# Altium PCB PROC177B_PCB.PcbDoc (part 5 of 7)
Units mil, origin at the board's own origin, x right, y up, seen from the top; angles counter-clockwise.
Board outline 4257.98 x 1561.15 mil, 4 copper layers (Top Layer, Int1 (GND), Int2 (PWR), Bottom Layer), stack 63.572 mil thick; 461 components, 307 nets, 1564 pads, 607 vias.
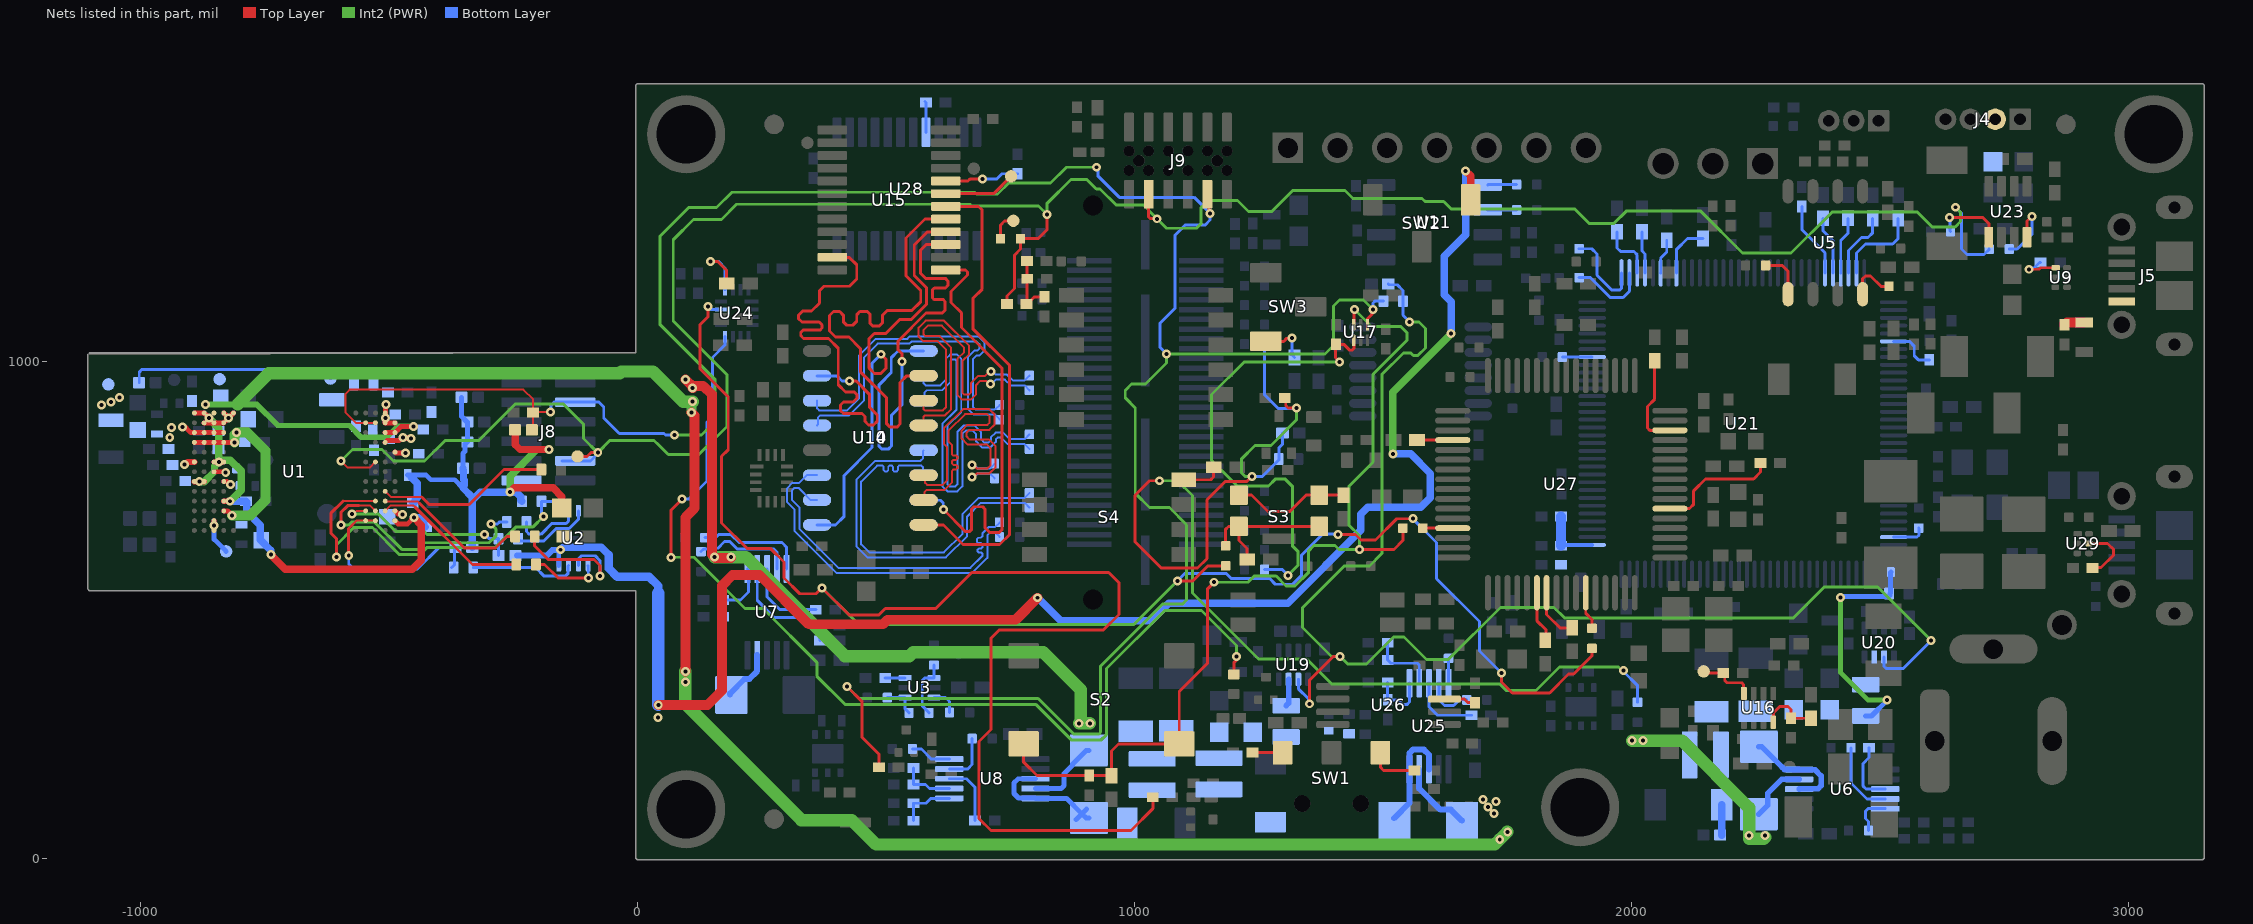
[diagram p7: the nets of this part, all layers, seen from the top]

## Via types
v1: diameter 18, hole 8, Top Layer to Bottom Layer, tented both sides, 603 vias
v2: diameter 19.68, hole 7.87, Top Layer to Bottom Layer, 4 vias

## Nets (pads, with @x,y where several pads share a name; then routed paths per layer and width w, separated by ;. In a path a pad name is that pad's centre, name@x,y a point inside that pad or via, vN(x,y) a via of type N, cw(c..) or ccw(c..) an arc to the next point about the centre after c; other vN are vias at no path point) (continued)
NetR16_2: R16.2 R206.2 R207.1 R208.2 | length 127.2
  Top Layer w5.9: R206.2@783.3,1115.15 785.27,1115.15 799.51,1129.39 R208.2@819.66,1129.39 ; R16.2@784.33,1201.3 784.33,1165.88 R207.1@784.59,1165.62 R206.2@784.59,1116.44
NetR18_2: R18.2 U23.1 | length 140.4
  Top Layer w5.9: v1(2640.07,1288.88) 2640.35,1288.6 2707.3,1288.6 2719.11,1276.8 U23.1@2719.11,1249.24
  Bottom Layer w5.9: v1(2640.07,1288.88) 2641.14,1287.82 2641.14,1262.05 R18.2@2642.2,1260.98
NetR19_2: R19.2 U23.4 | length 140
  Top Layer w5.9: U23.4@2795.88,1249.24 2795.88,1281.65 2805.38,1291.16 v1(2805.62,1291.16)
  Bottom Layer w5.9: R19.2@2760.28,1225.35 2776.11,1225.35 2805.62,1254.86 v1(2805.62,1291.16)
NetR25_1: R25.1 U6.5 | length 83.7
  Bottom Layer w5.9: R25.1@2477.18,55.6 2477.18,73.67 2470.87,79.98 2470.87,94.72 2475.82,99.67 U6.5@2510.78,99.67
NetR29_1: R29.1 U6.4 | length 152.7
  Bottom Layer w5.9: R29.1@2442.08,222.2 2442.08,151.44 2474.16,119.36 U6.4@2510.78,119.36
NetR33_2: R33.2 U24.13 | length 144.7
  Top Layer w5.9: v1(147.43,1200.04) 162.59,1200.04 180.11,1182.52 R33.2@180.11,1156.14
  Bottom Layer w5.9: v1(147.43,1200.04) 164.32,1200.04 176.78,1187.57 U24.13@176.78,1143.67
NetR45_1: R45.1 U2.5 | length 141.1
  Top Layer w5.9: R45.1@-203.66,591.06 -186.35,591.06 -159.4,564.1 v1(-98.28,564.1)
  Bottom Layer w5.9: U2.5@-98.86,588.39 -98.41,587.94 -98.41,564.23 v1(-98.28,564.1)
NetR46_2: R46.2 U2.2 | length 138
  Bottom Layer w6: R46.2@-222.82,676.58 -222.82,657.38 -217.43,652 -193,652 -171.8,673.2 -142.8,673.2 -137.9,678.1 U2.2@-137.9,698.95
NetR47_2: R47.2 U2.3 | length 158.8
  Bottom Layer w5.9: R47.2@-239.59,642.85 -234.53,637.78 -188.25,637.78 -162.79,663.25 -136.81,663.25 -118.22,681.85 U2.3@-118.22,698.95
NetR48_1: R48.1 U2.6 | length 282.8
  Top Layer w5.9: R48.1@-206.11,647.29 -206.11,628.4 -178.8,601.1 -87.03,601.1 -74.55,588.62 v1(-74.55,567.71)
  Bottom Layer w5.9: U2.6@-118.22,588.71 -118.22,602.49 -112.18,608.52 -84.5,608.52 -74.55,598.58 v1(-74.55,567.71)
NetR51_1: R51.1 U2.7 | length 216.5
  Bottom Layer w5.9: R51.1@-329.74,584.82 -204.43,584.82 -186.96,567.36 -144.66,567.36 -138.75,573.27 -138.75,587.87 U2.7@-137.9,588.71
NetR54_1: R54.1 U3.3 | length 40
  Bottom Layer w5.9: R54.1@498.95,362.69 U3.3@538.95,362.69
NetR55_2: R55.2 U3.6 | length 56.7
  Bottom Layer w5.9: U3.6@597.22,323.32 620.3,323.32 628.46,315.16 R55.2@628.46,293.12
NetR56_2: R56.2 R151.1 U3.1 | length 70
  Bottom Layer w5.9: R56.2@503.22,323.15 503.31,323.24 538.87,323.24 U3.1@538.95,323.32 538.95,300.75 546.82,292.88 R151.1@546.82,292.39
NetR57_1: R57.1 R151.2 U3.4 | length 122.7
  Bottom Layer w5.9: R151.2@587.17,292.39 587.17,292.88 573.51,306.54 573.51,357.59 578.61,362.69 U3.4@597.22,362.69 597,362.91 R57.1@597,388.66
NetR70_1: R70.1 S4.8 | length 81.4
  Top Layer w5.9: S4.8@1099.68,761.36 1153.76,761.36 1159.61,767.21 R70.1@1159.61,786.29
NetR72_2: R72.2 U9.1 | length 88.4
  Top Layer w5.9: v1(2799.93,1184.83) 2819.83,1184.83 2822.94,1187.94 U9.1@2857.94,1187.94
  Bottom Layer w5.9: v1(2799.93,1184.83) 2802.25,1187.14 2809.89,1187.14 2821.34,1198.6 R72.2@2823.31,1198.6
NetR78_2: R78.2 U5.1 | length 96.1
  Top Layer w5.9: R78.2@2270.11,1192.52 2303.76,1192.52 2315.27,1181 U5.1@2315.27,1134.88
NetR80_2: R80.2 U5.4 | length 95.1
  Top Layer w5.9: U5.4@2465.27,1134.88 2465.27,1165.84 2470.97,1171.54 2481.14,1171.54 2502.08,1150.59 R80.2@2518.4,1150.59
NetR83_2: R83.2 SW3.3 | length 96.6
  Top Layer w5.9: SW3.3@1264.64,1040.37 1265.47,1039.53 1300.53,1039.53 1307,1046 1317.13,1046 v1(1317.26,1046.12)
  Bottom Layer w5.9: v1(1317.26,1046.12) 1317.26,1012.73 R83.2@1322.56,1007.42
NetR93_2: R93.2 U1.E2 | length 350.3
  Top Layer w4: U1.E2@-506.87,738.15 -495.62,726.9 -433.56,726.9
  Top Layer w5.9: -433.56,726.9 -418.35,711.69 -337.98,711.69 -267.78,781.9 R93.2@-196.58,781.9
NetR94_2: R94.2 U6.3 | length 129.1
  Bottom Layer w5.9: R94.2@2478.02,222.27 2478.02,202.58 2466.3,190.86 2466.3,144.96 2472.22,139.04 U6.3@2510.78,139.04
NetR104_1: R104.1 R113.2 U7.2 | length 240.1
  Bottom Layer w5.9: U7.2@241.62,581.8 241.62,518.78 276.54,483.86 322.49,483.86 338.56,467.79 R104.1@367.76,467.79 R113.2@367.76,437.96
NetR105_1: R105.1 R114.2 U7.1 | length 138.6
  Bottom Layer w5.9: R105.1@172.68,485.6 R114.2@172.68,519.6 207.7,519.6 223.77,535.66 223.77,579.97 U7.1@221.94,581.8
NetR106_1: R106.1 R116.2 U8.2 | length 108.8
  Bottom Layer w5.9: R116.2@555.68,181.6 R106.1@555.68,148.6 580,148.6 588.37,140.23 U8.2@628.05,140.23
NetR107_1: R107.1 R117.2 U8.1 | length 111.5
  Bottom Layer w5.9: R117.2@555.68,75.6 R107.1@555.68,110.6 580.91,110.6 590.84,120.53 U8.1@628.05,120.54
NetR108_1: R108.1 U7.5 | length 221.2
  Bottom Layer w5.9: R108.1@136.19,644.91 157.8,644.91 163.76,650.87 189.13,650.87 204.87,635.13 291.16,635.13 300.68,625.62 U7.5@300.68,581.8
NetR109_1: R109.1 U8.5 | length 82.8
  Bottom Layer w5.9: R109.1@553.74,219.86 571.74,219.86 592.31,199.28 U8.5@628.05,199.28
NetR110_1: R110.1 U7.4 | length 203.6
  Bottom Layer w5.9: R110.1@128.61,616.82 134.08,622.29 147.3,622.29 148.56,623.55 162.53,623.55 175.9,636.92 186.25,636.92 200.64,622.53 274.52,622.53 280.99,616.06 U7.4@280.99,581.8
NetR111_1: R111.1 U8.4 | length 101.6
  Bottom Layer w5.9: U8.4@628.05,179.6 665,179.6 673.82,188.43 R111.1@673.82,240.6
NetR112_2: R112.2 U7.3 | length 164.6
  Bottom Layer w5.9: U7.3@261.31,581.8 261.31,525.98 287.28,500 R112.2@359.34,500
NetR115_2: R115.2 U8.3 | length 125.6
  Bottom Layer w5.9: U8.3@628.05,159.91 662.69,159.91 679.84,142.76 R115.2@679.84,76.05
NetR122_1: R122.1 U21.35 | length 114.9
  Bottom Layer w5.9: R122.1@1971.24,1260.16 1971.24,1227.81 1978.71,1220.34 2005.3,1220.34 2011.8,1213.85 U21.35@2011.8,1177.6
NetR124_1: R124.1 U21.36 | length 85.2
  Bottom Layer w5.9: R124.1@2021.22,1260.16 2021.22,1221.93 2027.55,1215.6 U21.36@2027.55,1177.6
NetR125_1: R125.1 U21.38 | length 70.4
  Bottom Layer w5.9: U21.38@2059.04,1177.6 2059.17,1177.73 2059.17,1207.38 2071.2,1219.4 R125.1@2071.2,1242.93
NetR126_1: R126.1 U21.40 | length 109.5
  Bottom Layer w5.9: U21.40@2090.54,1177.6 2090.54,1224.17 2113.12,1246.75 R126.1@2144.09,1246.75
NetR135_1: R135.1 R148.2 U25.2 | length 139.1
  Bottom Layer w5.9: R148.2@1509.86,433.69 R135.1@1509.86,398.71 1516.33,392.24 1569.81,392.24 1573.27,388.78 U25.2@1573.27,352.18
NetR136_1: R136.1 R150.2 U25.1 | length 122.9
  Bottom Layer w5.9: R136.1@1509.86,353.71 R150.2@1509.86,318.71 1530.55,318.71 1540.39,308.87 1548.16,308.87 1553.58,314.3 U25.1@1553.58,352.18
NetR137_1: R137.1 U25.5 | length 50
  Bottom Layer w5.9: U25.5@1632.32,352.18 R137.1@1632.32,402.18
NetR139_1: R139.1 U25.4 | length 98.7
  Bottom Layer w5.9: U25.4@1612.64,352.18 1612.92,351.9 1612.92,318.43 1623.85,307.5 1642.51,307.5 1653.93,318.92 R139.1@1668.51,318.92
NetR142_2: R142.2 U25.3 | length 140
  Bottom Layer w5.9: U25.3@1592.95,352.18 1592.95,304.65 1610,287.6 R142.2@1678.31,287.6
NetR159_1: R159.1 U11.6 | length 58.3
  Bottom Layer w5.9: U11.6@1711.14,1304.47 1711.51,1304.1 R159.1@1769.3,1304.1
NetR160_1: R160.1 U11.5 | length 58.5
  Bottom Layer w5.9: U11.5@1711.14,1354.47 1712.04,1355.38 R160.1@1769.3,1355.38
NetR170_1: R170.1 U21.95 | length 66.9
  Bottom Layer w5.9: U21.95@2527.55,646.1 2574.77,646.1 2578.53,649.85 2578.53,663.62 R170.1@2578.12,664.03
NetR181_2: R181.2 U21.33 | length 177.2
  Bottom Layer w5.9: R181.2@1895.06,1226.06 1920.17,1226.06 1930.64,1215.58 1930.64,1172.96 1960.63,1142.97 1976.85,1142.97 1980.3,1146.43 U21.33@1980.3,1177.6
NetR185_2: R185.2 U26.3 | length 64.8
  Top Layer w5.9: U26.3@1623.99,320.19 1663.91,320.19 1670.4,313.7 1684.73,313.7 R185.2@1685.72,312.7
NetR188_2: R188.2 U21.34 | length 159.5
  Bottom Layer w5.9: R188.2@1895.07,1167.93 1917.94,1167.93 1957.62,1128.25 1983.62,1128.25 1996.05,1140.68 U21.34@1996.05,1177.6
NetR190_2: R190.2 U21.25 | length 60
  Bottom Layer w5.9: R190.2@1861.25,1008.31 U21.25@1921.25,1008.31
NetR191_1: R191.1 U21.63 | length 176
  Bottom Layer w5.9: U21.63@2452.74,1177.6 2452.74,1217.35 2471.07,1235.67 2525.66,1235.67 2536.85,1246.87 R191.1@2536.85,1286.8
NetR194_1: R194.1 U21.62 | length 136.8
  Bottom Layer w5.9: U21.62@2437,1177.6 2437,1222.6 2463,1248.6 2475.83,1248.6 2485.43,1258.2 R194.1@2485.43,1286.8
NetR195_1: R195.1 U21.61 | length 115.7
  Bottom Layer w5.9: U21.61@2421.25,1177.6 2421.25,1242.42 2436.08,1257.25 R195.1@2436.08,1287.14
NetR196_1: R196.1 U21.60 | length 117.8
  Bottom Layer w5.9: R196.1@2385.51,1287.14 2385.51,1262.34 2405.5,1242.35 U21.60@2405.5,1177.6
NetR213_1: R213.1 S3.3 S3.4 | length 237.6
  Top Layer w5.9: S3.4@1210.66,730.49 1236.14,730.49 1269.21,697.43 1312.82,697.43 1345.89,730.49 S3.3@1372.08,730.49 R213.1@1420.9,730.49
NetR214_1: R214.1 R215.1 S3.1 S3.2 | length 297.2
  Top Layer w5.9: R214.1@1184,628.54 1184,661.93 1189.58,667.5 S3.2@1210.66,667.5 ; R215.1@1227.05,600.84 1227.05,623 1210.66,639.4 S3.2@1210.66,667.5 ; S3.1@1372.08,667.5 S3.2@1210.66,667.5
NetR231_1: R231.1 U21.70 | length 98.4
  Bottom Layer w5.9: U21.70@2527.55,1039.81 2559.36,1039.81 2569.16,1030 2569.16,1010.95 2577.38,1002.73 R231.1@2599.45,1002.73
NetR234_2: R234.2 U21.59 | length 152.9
  Bottom Layer w5.9: R234.2@2342.87,1311.08 2342.87,1264.73 2389.75,1217.85 U21.59@2389.75,1177.6
NetR242_1: R242.1 U27.59 | length 76.7
  Top Layer w5.9: U27.59@1908.32,534.06 1908.32,492.71 1920.74,480.3 R242.1@1920.74,462.51
NetR251_1: R251.1 U27.36 | length 71.8
  Top Layer w5.9: R251.1@1568.79,841.15 U27.36@1640.61,841.15
NetR260_2: R260.2 U29.5 | length 118.8
  Top Layer w5.9: U29.5@2920.73,633.09 2958.12,633.09 2970.36,620.85 2970.36,610.29 2944.87,584.8 2928.39,584.8 R260.2@2927.66,584.07
NRST_FTDI: R243.1 U27.45 | length 60
  Top Layer w5.9: R243.1@1580.61,663.99 U27.45@1640.61,663.99
PGOOD: R58.1 R179.1 R198.1 R201.2 R241.1 | length 2441.1
  Top Layer w5.9: v1(1050.82,759.39) 1030.81,759.39 1001.55,730.13 1001.55,636.49 1054.29,583.76 1127.19,583.76 1146.12,602.68 1146.12,721.1 1183.33,758.31 1226.93,758.31 1236.44,767.82 v1(1236.44,767.93) ; R179.1@1302.99,925.75 1304.79,923.95 1304.79,910.51 1309.48,905.83 v1(1326.6,905.83)
  Int2 (PWR) w5.9: v1(1050.82,759.39) 1087.71,759.39 1117.26,729.84 1117.26,533.58 1249.84,401 1346.94,401 1397.01,350.93 1735.05,350.93 1748.36,337.62 1808.26,337.62 1855.27,384.64 1973.95,384.64 1980.96,377.64 v1(1984.11,377.64) ; v1@1236.28,768.08 1223.14,768.08 1215.32,775.91 1215.32,802.82 1242.83,830.33 1274.89,830.33 1326.6,882.05 v1(1326.6,905.83)
  Bottom Layer w5.9: v1(1236.44,767.93) 1257.68,767.93 1290.81,801.06 1290.81,825.16 1298.43,832.78 R201.2@1298.43,855.52 ; R58.1@1262.19,1034.29 1262.19,932.26 1289.42,905.03 1325.81,905.03 v1(1326.6,905.83) ; v1(1984.11,377.64) 1984.11,375.5 2012.67,346.94 2012.67,314.14 R241.1@2012.34,313.81
PMIC_CLKOUT: R15.2 TP1.1 | length 56.6
  Top Layer w5.9: R15.2@730.92,1246.42 730.92,1273.51 739.07,1281.66 756,1281.66 TP1.1@756.73,1282.4
PMIC_CLKOUT_LIN_PHY_TX_SOP1: J8.4 J9.3 R15.1 R19.1 R206.1 TP13.1 U1.H3 | length 4957
  Top Layer w4: v1(-595.63,799.05) -582.15,785.57 -538.19,785.57 U1.H3@-526.56,797.2
  Top Layer w5.9: TP13.1@-119.98,808.16 -100.84,808.16 -93.1,815.9 v1(-79.24,815.9) ; R206.1@743.93,1115.15 743.93,1131.09 759.04,1146.2 759.04,1213.19 771.27,1225.41 R15.1@771.27,1246.42 806.49,1246.42 824.85,1264.78 v1(824.85,1295) ; J9.3@1028.99,1335.77 1028.99,1289.98 1032.45,1286.53 v1@1045.9,1286.53
  Int2 (PWR) w5.9: v1(-595.63,799.05) -572.55,822.12 -513.3,822.12 -490.18,799.01 -427.58,799.01 -386.58,840 -319.28,840 -245.79,913.49 -163.25,913.49 -148.05,913.49 -107.67,873.11 -107.67,844.34 v1(-79.24,815.9) -54.41,840.74 32.47,840.74 32.62,840.59 34.13,840.59 43.64,831.08 62.7,812.01 124.04,812.01 180.78,868.76 180.78,972.62 72.66,1080.74 72.66,1244.11 113.6,1285.05 169.52,1285.05 200.06,1315.59 669.41,1315.59 672.77,1312.24 807.62,1312.24 v1(824.85,1295) 824.85,1317.82 872.65,1365.62 904.56,1365.62 923.67,1346.51 931.15,1346.51 963.76,1313.9 1018.53,1313.9 v1(1046.03,1286.4) 1065.04,1267.39 1125.21,1267.39 1134.69,1276.87 1134.69,1309.12 1148.65,1323.07 1207.94,1323.07 1229.84,1301.18 1276.78,1301.18 1318.84,1343.23 1424.12,1343.23 1440.19,1327.17 1579.08,1327.17 1585.31,1320.94 1622.47,1320.94 1637,1306.41 1885.64,1306.41 1915.38,1276.66 1964.62,1276.66 1989.62,1301.65 2139.59,1301.65 2223.81,1217.43 2321.45,1217.43 2403.63,1299.62 2575.78,1299.62 2605.31,1270.09 2651.47,1270.09 2662.21,1280.83 2662.21,1299.56 v1(2652.17,1309.61)
  Bottom Layer w5.9: J8.4@-150.85,799.4 J8.4@-124.58,799.4 -94.07,799.4 -79.24,814.23 v1(-79.24,815.9) ; v1(2652.17,1309.61) 2664.21,1297.57 2664.21,1225.69 2675.41,1214.5 2709.56,1214.5 2719.92,1224.86 R19.1@2719.92,1225.35
QSPI_CS: R50.2 U1.D3 U2.1 | length 784.2
  Top Layer w4: -591.91,718.26 U1.D3@-526.76,718.26
  Top Layer w5.9: v1(-604.99,605.87) -604.99,642.83 -616.25,654.09 -616.25,693.92 -591.91,718.26
  Int2 (PWR) w5.9: v1(-604.99,605.87) -604.99,630.38 -570.31,665.07 -532.68,665.07 -478.94,611.33 -436.83,611.33 -423.46,624.7 -285.52,624.7 -244.17,666.05 -210.18,666.05 v1(-188.64,687.59)
  Bottom Layer w5.9: R50.2@-192.32,717.93 -161.94,717.93 -157.59,713.57 U2.1@-157.59,698.95 ; R50.2@-192.2,717.8 -192.2,693.86 -188.64,690.3 v1(-188.64,687.59)
QSPI_D0: R45.2 U1.C2 | length 313.9
  Top Layer w4: U1.C2@-506.87,698.78 -495.61,710.04 -450.46,710.04 -446.57,706.16
  Top Layer w5.9: -446.57,706.16 -331.48,591.06 R45.2@-246.96,591.06
QSPI_D1: R46.1 U1.C3 | length 515.1
  Top Layer w4: -559.75,709.31 -559.22,709.83 -537.61,709.83 U1.C3@-526.56,698.78
  Top Layer w5.9: v1(-595.52,670.61) -595.52,696.2 -582.41,709.31 -559.75,709.31
  Int2 (PWR) w5.9: v1(-595.52,670.61) -580.27,670.61 -574.83,676.05 -528.11,676.05 -473.47,621.41 -440.75,621.41 -427.56,634.6 -297.81,634.6 -283.59,648.83 -283.59,661.62 v1(-294.45,672.47)
  Bottom Layer w5.9: v1(-294.45,672.47) -280.97,672.47 -277.42,676.02 -262.75,676.02 R46.1@-262.19,676.58
QSPI_D2: R44.1 R47.1 U1.C4 | length 379
  Top Layer w4: v1(-573.43,692.83) -569.64,692.83 -563.69,698.78 U1.C4@-546.24,698.78
  Int2 (PWR) w5.9: v1(-573.43,692.83) -521.25,692.83 -486.02,657.6 -428.9,657.6 -422.79,651.49 v1(-307.01,651.49)
  Bottom Layer w5.9: v1(-307.01,651.49) -306.3,651.49 -297.66,642.85 R47.1@-278.96,642.85 -278.96,609.26 R44.1@-278.56,608.86
QSPI_D3: R49.1 R51.2 U1.B3 U1.B4 | length 409.5
  Top Layer w4: -572.63,671.09 -564.62,679.09 U1.B3@-526.56,679.09
  Top Layer w5.9: v1(-580.2,609.1) -580.51,609.41 -580.51,663.39 -572.82,671.09 -572.63,671.09
  Bottom Layer w5.9: v1(-580.2,609.1) -580.2,592.18 -569.65,581.62 -442.02,581.62 -398.19,625.44 -368.27,625.44 -367.55,624.72 -367.55,590.32 R51.2@-373.05,584.82
QSPI_SCLK: R48.2 U1.D2 | length 309.9
  Top Layer w4: U1.D2@-506.84,718.5 -506.38,718.04 -441.62,718.04 -437.71,714.13
  Top Layer w5.9: -437.71,714.13 -347.85,624.27 -284.85,624.27 -261.82,647.29 R48.2@-245.48,647.29
RADAR_1P2_RF: C20.2 C24.2 C44.1 C101.2 R134.2 TP16.1 U1.L7 U1.L8 U1.L9 U1.L10 U25.9 | length 239.3
  Top Layer w10: v1(-915.04,867.23) -913.89,866.09 -907.8,866.09 -897.98,856.26 U1.L9@-871.04,856.26 U1.L8@-851.36,856.26 U1.L7@-831.67,856.26
  Bottom Layer w12: U25.9@1573.27,178.95 1573.27,140.27 1615.72,97.82 1636.87,97.82 R134.2@1659.17,75.52
  other v1: 1724.05,90.44 1711.42,103.17 1727.65,114.48 1701.87,118.61 -940.29,846.58 -937.03,866.57 -1077.9,912.16 -1058.76,917.66 -1041.29,926.5
RADAR_1V2: C27.2 C28.2 C29.2 C30.1 C45.1 R77.2 R86.2 R193.2 TP15.1 U1.K2 U8.9 | length 2001.4
  Top Layer w10: U1.K2@-506.87,836.57 -503.43,840.02 -479.09,840.02 -473.25,845.85 v1@-470.97,845.85
  Top Layer w12: v1(-470.97,846.51) -470.2,845.75 -457.77,845.75 -456.34,844.31 v1(-455.26,844.31)
  Top Layer w15: v1(-470.97,846.51) v1@-470.7,846.51
  Top Layer w20: v1(97.5,963.14) 97.5,963.09 111.73,948.85 v1(111.73,946.37) ; v1@112.5,946.37 116.27,950.14 132.84,950.14 150.26,932.72 150.26,611.34 157.54,604.06 v1@188.58,604.06
  Int2 (PWR) w25: v1(156,605.6) v1(188.58,605.6) 218.73,605.6 417.91,406.43 547.48,406.43 555.14,414.08 817.17,414.08 892.23,339.02 v1@892.23,271.53 ; v1(888.85,271.53) v1@892.23,271.53 ; v1(910.85,271.53) v1@892.23,271.53
  Bottom Layer w5.9: R86.2@-1001.58,956.6 -1001.58,977.81 -995.86,983.53 -635.71,983.53 TP15.1@-617.14,964.95
  Bottom Layer w10: U8.9@801.28,140.23 852.96,140.23 858.82,146.09 858.82,170.3 875.72,187.2 875.72,189.41 903.2,216.89 R193.2@908.71,216.89
RADAR_1V4_APLL: C22.2 U1.G8 | length 22.8
  Top Layer w10: U1.G8@-851.36,777.52 -829.67,777.52 v1@-829.67,776.38
  other v1: -827.67,776.38
RADAR_1V4_SYNTH: C18.2 U1.F7 | length 16.5
  Top Layer w10: U1.F7@-831.67,757.83 -825.39,757.83 -819.28,751.73 v1(-817.66,751.73)
RADAR_1V8: C4.2 C5.2 C7.2 C8.2 C10.2 C11.2 C12.2 C13.1 C14.2 C15.1 R192.2 TP14.1 U1.B1 U1.D7 U1.F9 U1.F10 U1.H7 U1.H8 U1.L1 U1.L2 U1.M7 U1.M8 U1.M9 U1.N6 U1.N7 U1.N8 U1.N9 U1.N10 U6.9 | length 5504.3
  Top Layer w10: U1.N10@-890.73,895.63 -881.2,895.63 -880.89,895.31 -880.57,895.63 U1.N9@-871.04,895.63 v1(-861.2,885.79) ; U1.M9@-871.04,875.94 U1.M8@-851.36,875.94 -832.54,875.94 U1.M7@-832.27,875.67 ; U1.H8@-851.36,797.2 U1.H7@-831.67,797.2 ; U1.M7@-831.67,875.94 v1(-821.83,885.79) ; U1.N7@-831.67,895.63 v1(-821.83,885.79) ; U1.N6@-811.99,895.63 v1(-821.83,885.79) ; U1.L2@-506.87,856.26 U1.L1@-486.41,856.26 ; U1.B1@-487.19,679.09 -480.76,672.67 -461.47,672.67 v1(-448.8,685.34) ; U1.L1@-487.19,856.26 -481.5,861.94 -481.39,861.94 -474.67,868.66 v1(-450.25,868.66)
  Top Layer w11: U1.F10@-890.73,757.83 U1.F9@-871.04,757.83 ; U1.D7@-831.67,718.46 -819.06,718.46 v1(-818.76,718.16)
  Top Layer w15: v1(-736.28,610.68) -736.28,609.87 -707.6,581.2 -452.41,581.2 -434.01,599.6 -434.01,670.27 -448.8,685.07 v1(-448.8,685.34)
  Top Layer w20: v1(97,375.96) 96.98,685.87 115.35,704.24 115.35,890.53 v1(109.19,896.69)
  Int2 (PWR) w11: -765.27,913.22 -722.57,870.52 -578.72,870.52 -555.04,846.84 -504.11,846.84 -482.29,868.66 v1(-450.25,868.66)
  Int2 (PWR) w12: v1(-868.7,913.22) -803.76,913.22 -765.27,913.22
  Int2 (PWR) w15: v1(-880.89,757.52) -870.75,757.52 -850.23,778.04 -850.23,788.18 v1(-841.52,796.89) ; v1(-861.2,885.79) -861.2,884.97 -841.52,865.29 v1(-841.52,796.89) ; v1(-818.76,718.16) -796.75,740.16 -796.75,779.1 -818.43,800.78 -836.81,800.78 -840.7,796.89 v1(-841.52,796.89)
  Int2 (PWR) w20: v1(109.19,896.69) 109.19,916.05 v1(111.73,918.6)
  Int2 (PWR) w25: -803.76,913.22 -740.93,976.05 -35.04,976.05 -31.87,979.22 31.91,979.22 92.53,918.6 v1(111.73,918.6) ; v1(97,375.96) 96.94,375.9 v1(96.94,354.46) 96.94,310.27 330.42,76.78 431.55,76.78 480.68,27.65 1725.04,27.65 v1(1735.27,37.88) v1@1750.3,52.91 ; v1(2001.72,236.57) 2101.89,236.6 2237,101.5 2237,42 2237,39.02 2266.06,39.02 v1@2269.04,42
  Bottom Layer w11: R192.2@2256.59,88.69 2274.69,106.78 2274.69,131.22 2302.2,158.73 U6.9@2337.55,158.73
  Bottom Layer w15: v1(-818.76,718.16) C14.2@-786.88,718.18 -784.93,716.23 -784.93,696.66 -758.06,669.78 -758.06,640.36 -736.85,619.15 -736.85,611.25 v1(-736.28,610.68) ; v1(-448.8,685.34) -448.61,685.14 -438.04,685.14 -428.94,676.05 -428.94,668.65 -426.6,666.31 C7.2@-425.94,666.31
  other v1: 2237,46 2269.04,46 1751.33,52.91 2023.72,236.6
RADAR_1V_RF_OUT: C9.2 C19.2 C23.1 U1.C7 U1.K7 U1.K8 U1.K9 U1.K10 | length 375.2
  Top Layer w10: U1.K10@-890.73,836.57 U1.K9@-871.04,836.57 U1.K8@-851.36,836.57 U1.K7@-831.67,836.57 v1(-810.17,836.52) v1(-810.17,836.52) ; U1.C7@-831.67,698.78 -823.85,698.78 v1(-814.95,689.89)
  Int2 (PWR) w20: v1(-814.95,689.89) -777.53,689.89 -748.04,719.38 -748.04,820.17 -783.95,856.08 v1(-806.23,856.08) -810.17,852.14 v1(-810.17,836.52)
RADAR_3V3: C16.2 C17.2 C21.2 C34.1 C35.2 C43.1 J8.1 R4.2 R20.2 R44.2 R49.2 R50.1 R73.2 R74.2 R75.2 R200.2 SW2.1 U1.C1 U1.J1 U2.8 U7.9 | length 4589.4
  Top Layer w10: U1.C1@-487.19,698.78 -480.68,692.27 -473.24,692.27 v1(-472.09,691.13) ; U1.J1@-487.19,816.89 -485.3,815.01 v1(-465.87,815.01)
  Top Layer w15: v1(-255.67,736.62) -247.3,744.99 -168.85,744.99 -151.48,727.62 C35.2@-151.48,704.58 ; R20.2@-245.67,861.86 -245.67,832.27 -235.64,822.24 v1(-177.61,822.24) ; v1(1666.78,1382.71) 1666.78,1382.29 1676.53,1372.54 SW2.1@1676.53,1324.48
  Top Layer w20: v1(42.47,308.38) 141.77,308.38 170.66,337.26 170.66,548.23 192.01,569.58 246.33,569.58 345.14,470.77 494.5,470.77 503.56,479.82 761.44,479.82 v1(805.66,524.05)
  Int2 (PWR) w15: v1(-255.67,736.62) -255.67,768.53 -201.96,822.24 v1(-177.61,822.24) ; v1(1520.16,813.4) 1520.16,937.82 1637.49,1055.15 v1(1637.49,1055.81)
  Bottom Layer w9: U2.8@-157.59,588.71 -157.59,615.34 -154.21,618.71 v1(-154.21,620.6)
  Bottom Layer w10: C17.2@-461.85,770.72 -424.55,770.72 -415.25,761.43 -366.94,761.43 -350.36,744.85 ; R74.2@-353.48,927.39 -353.48,889 -342.22,877.74 R75.2@-341.38,877.74 -341.49,877.64 -341.49,837.64 R4.2@-341.59,837.53 -346.18,832.94 -346.18,818.65 -350.36,814.48 R73.2@-350.36,784.56
  Bottom Layer w12: R44.2@-242,608.86 -181.76,608.86 -170.78,619.84 -154.98,619.84 v1(-154.21,620.6) ; R200.2@186.98,329.41 186.98,331.47 215.99,360.48 225.69,360.48 241.53,376.31 241.53,408.48 U7.9@241.62,408.58
  Bottom Layer w15: C17.2@-454.49,766.41 -442.13,754.05 -442.13,725.51 -446.91,720.73 -446.91,716.72 -449.25,714.38 C16.2@-451.22,714.38 ; R73.2@-350.36,784.56 -350.36,781.82 -349.34,780.8 -349.34,761.51 -348.03,760.2 -348.03,749.84 -350.36,747.51 -350.36,744.85 -331.72,726.21 ; R49.2@-331.72,625.44 -331.72,726.21 ; R50.1@-231.69,717.93 -234.03,720.27 -234.03,727.55 -243.11,736.62 v1(-255.67,736.62) -315.68,736.62 -328.9,723.4 -331.72,726.21 ; v1(-154.21,620.6) -153.94,620.6 -148.74,625.81 -72.54,625.81 -56.87,610.13 ; v1(805.66,524.05) 851.84,477.87 1034.17,477.87 1069.56,513.27 1309.25,513.27 1455.69,659.71 1455.69,691.88 1469.81,706 1576.72,706 1595.75,725.03 1595.75,773.96 1556.31,813.4 v1(1520.16,813.4) ; v1(1637.49,1055.81) 1637.65,1055.98 1637.65,1119.66 1623.88,1133.44 1623.88,1172.1 1623.43,1172.54 1623.43,1211.2 1666.78,1254.55 v1(1666.78,1382.71)
  Bottom Layer w17: -56.87,610.13 -56.87,582.87 -40.25,566.25 23.99,566.25 42.58,547.66 42.58,533.02
  Bottom Layer w25: v1(42.47,308.38) 42.47,532.91 42.58,533.02
  other v1: 42.03,283.22
RADAR_LVDS_0M: R230.2 U10.3 | length 675.4
  Bottom Layer w4: U10.3@361.83,770.53 341.33,770.53 325.76,754.96 312.35,754.96 301.56,744.18 301.56,716.34 316.25,701.65 316.25,658.63 400.76,574.12 674.51,574.12 704.69,604.3 704.69,649.62 710.96,655.9 719.71,655.9 729.06,646.55 R230.2@729.06,646.05
RADAR_LVDS_0P: R229.2 U10.2 | length 675.4
  Bottom Layer w4: U10.2@361.83,720.53 349.02,720.53 324.59,744.96 316.49,744.96 311.56,740.03 311.56,720.48 326.25,705.79 326.25,662.77 404.9,584.12 670.37,584.12 694.69,608.44 694.69,612.63 692.34,614.97 687.42,614.97 685.08,617.32 685.08,620.63 687.75,623.3 692.34,623.3 694.69,625.64 694.69,630.83 691.12,634.4 685.6,634.4 683.26,636.74 683.26,642.05 685.95,644.74 691.53,644.74 694.69,647.89 694.69,653.77 706.82,665.9 719.71,665.9 729.06,675.25 R229.2@729.06,675.74
RADAR_LVDS_1M: R228.2 U10.13 | length 733.2
  Bottom Layer w4: U10.13@576.39,820.53 575.5,819.64 575.5,805.06 570.05,799.61 478.78,799.61 440.78,761.61 440.78,627.39 462.95,605.22 621.19,605.22 664,648.03 664,687.48 691.47,714.95 779.71,714.95 789.06,705.6 R228.2@789.06,705.11
RADAR_LVDS_1P: R227.2 U10.14 | length 733.5
  Bottom Layer w4: U10.14@576.39,770.53 575.15,771.77 575.15,786 571.54,789.61 526.98,789.61 524.64,787.27 524.64,780.59 522.3,778.25 516.96,778.25 514.62,780.59 514.62,787.27 512.28,789.61 507.46,789.61 505.12,787.27 505.12,780.49 502.78,778.15 498.59,778.15 495.91,780.82 495.91,787.27 493.57,789.61 482.93,789.61 450.78,757.47 450.78,631.54 467.1,615.22 617.05,615.22 654,652.17 654,691.62 687.33,724.95 779.71,724.95 789.06,734.3 R227.2@789.06,734.79
RADAR_LVDS_2M: R224.2 U10.11 | length 733.6
  Bottom Layer w4: U10.11@576.05,920.87 577.63,922.44 577.63,936.34 582.74,941.45 614.07,941.45 619.93,947.31 630.83,958.21 630.83,1000.41 633.68,1003.26 639.6,1003.26 641.98,1000.88 641.98,901.73 614,873.74 614,748.5 624.29,738.2 644.32,738.2 654.38,748.26 654.38,853.53 661.62,860.78 674.31,860.78 681.97,853.12 681.97,838.54 691.33,829.17 694.26,826.25 710.32,826.25 721.48,837.41 721.48,842.53 725.21,846.26 732.01,846.26 745.21,833.06 779.71,833.06 789.06,823.71 R224.2@789.06,823.22
RADAR_LVDS_2P: R223.2 U10.10 | length 733.4
  Bottom Layer w4: U10.10@576.39,970.53 576.39,955.4 580.35,951.45 609.93,951.45 620.83,962.35 620.83,1004.55 629.54,1013.26 643.74,1013.26 651.98,1005.03 651.98,907.58 651.98,897.58 624,869.6 624,752.64 628.44,748.2 640.18,748.2 644.38,752.41 644.38,857.68 657.48,870.78 678.46,870.78 691.97,857.26 691.97,842.68 698.4,836.25 706.18,836.25 711.48,841.55 711.48,846.67 721.07,856.26 736.15,856.26 749.35,843.06 779.71,843.06 789.06,852.41 R223.2@789.06,852.9
RADAR_LVDS_3M: R222.2 U10.5 | length 673.5
  Bottom Layer w4: U10.5@361.83,870.53 363.4,872.1 363.4,886 368.51,891.11 426.56,891.11 456.39,920.94 456.39,1007.46 483.96,1035.02 547.55,1035.02 551.87,1039.34 683.07,1039.34 688.4,1034.02 688.4,1025.36 684.85,1021.81 679.31,1021.81 665.12,1007.62 665.12,904.25 676.41,892.96 718.86,892.96 729.06,882.77 R222.2@729.06,882.27
RADAR_LVDS_3P: R221.2 U10.6 | length 673
  Bottom Layer w4: U10.6@361.83,920.53 362.17,920.19 362.17,905.06 366.12,901.11 422.42,901.11 446.39,925.08 446.39,1011.6 479.82,1045.02 543.41,1045.02 547.73,1049.34 687.22,1049.34 698.4,1038.16 698.4,1021.21 688.99,1011.81 683.45,1011.81 675.12,1003.48 675.12,908.4 680.55,902.96 719.37,902.96 720.52,904.12 721.71,904.12 729.06,911.47 R221.2@729.06,911.96
RADAR_LVDS_CLK: U14.1 U15.18 | length 965.1
  Top Layer w5.9: U14.1@576.39,670.53 616.11,670.53 655.55,631.09 729.1,631.09 749.32,651.32 749.32,991.16 675.32,1065.16 675.32,1125.98 694.07,1144.74 694.07,1304.18 686.92,1311.33 U15.18@620.85,1311.33
RADAR_LVDS_CLKM: R226.2 U14.3 | length 603.2
  Top Layer w4: U14.3@576.39,770.53 579.54,767.39 579.54,755.06 583.48,751.12 614.43,751.12 622.99,759.68 622.99,801.34 622.99,827.4 616.79,833.6 616.79,864.77 655.6,903.58 708.17,903.58 718.87,892.89 718.87,872.35 708.46,861.94 668.4,861.94 662.58,856.12 662.58,848.61 668.49,842.7 707.25,842.7 721.1,828.85 721.1,786.76 708.35,774.01 683.28,774.01 676.28,767.01 v1(673.94,767.01)
  Bottom Layer w4: v1(673.94,767.01) 677.72,767.01 684.72,774.01 709.71,774.01 719.06,764.66 R226.2@719.06,764.16
RADAR_LVDS_CLKP: R225.2 U14.2 | length 602.9
  Top Layer w4: U14.2@576.39,720.53 577.67,721.81 577.67,736 582.79,741.12 618.57,741.12 632.99,755.54 632.99,778.68 636.42,782.11 641.69,782.11 644.59,785.01 644.59,788.69 641.96,791.32 636.05,791.32 633.71,793.66 633.71,798.82 636.05,801.16 641.1,801.16 643.99,804.05 643.99,807.73 641.36,810.36 635.33,810.36 632.99,812.71 632.99,831.55 626.79,837.74 626.79,860.63 659.74,893.58 704.03,893.58 708.87,888.74 708.87,876.49 704.31,871.94 664.25,871.94 652.58,860.26 652.58,844.47 664.35,832.7 703.11,832.7 711.1,824.71 711.1,790.9 704.21,784.01 683.28,784.01 676.28,791.01 v1(673.94,791.01)
  Bottom Layer w4: v1(673.94,791.01) 677.72,791.01 684.72,784.01 709.71,784.01 719.06,793.36 R225.2@719.06,793.85
RADAR_LVDS_DATA0: U10.1 U15.16 | length 901.6
  Top Layer w5.9: v1(490.56,1013.88) 500.92,1003.51 500.92,986.11 490.01,975.21 477.61,975.21 466,986.82 466,1044.45 477.15,1055.6 500.3,1055.6 528.3,1083.6 551.38,1083.6 582.46,1114.68 582.46,1147.04 557.49,1172.01 557.49,1233.71 583.93,1260.15 U15.16@620.85,1260.15
  Bottom Layer w5.9: U10.1@361.83,670.53 399,670.53 416.46,687.99 416.46,770.06 472.4,826.01 472.4,995.72 v1(490.56,1013.88)
RADAR_LVDS_DATA1: U10.15 U15.13 | length 902
  Top Layer w5.9: v1(616,701.6) 660.67,656.93 668.13,656.93 672.98,661.78 672.98,702.3 677.7,707.02 695.08,707.02 700,702.11 700,664.67 709.37,655.3 728.37,655.3 734.38,661.31 734.38,985.44 652.32,1067.5 652.32,1097.18 631.39,1118.1 631.39,1140.33 664.6,1173.54 664.6,1179.19 660.4,1183.38 U15.13@620.85,1183.38
  Bottom Layer w5.9: U10.15@576.39,720.53 576.7,720.22 610.24,720.22 615.7,714.75 615.7,701.9 v1(616,701.6)
RADAR_LVDS_DATA2: U10.9 U15.15 | length 901.3
  Top Layer w5.9: v1(533.08,999.3) 533.08,1014.33 524.62,1022.79 524.62,1040 581.21,1096.6 613.77,1096.6 619.49,1102.32 619.49,1120.15 616.04,1123.6 597.82,1123.6 594.36,1127.06 594.36,1143.81 597.82,1147.27 620.08,1147.27 624.94,1152.12 624.94,1161.42 619.79,1166.57 580.25,1166.57 570.14,1176.68 570.14,1223.17 581.53,1234.56 U15.15@620.85,1234.56
  Bottom Layer w5.9: v1(533.08,999.3) 533.08,912.51 511.88,891.31 511.88,829.28 506.28,823.67 491.71,823.67 486.83,828.56 486.83,952.71 511.12,977 511.12,1006.8 524.84,1020.53 U10.9@576.39,1020.53
RADAR_LVDS_DATA3: U10.7 U15.11 | length 902.5
  Top Layer w5.9: U15.11@392.51,1208.97 393.4,1208.07 427.43,1208.07 441.76,1193.74 441.76,1165.17 427.24,1150.65 376.05,1150.65 367,1141.6 367,1116.6 351,1100.6 333,1100.6 324.72,1092.33 324.72,1085.32 331.33,1078.71 366.2,1078.71 371.77,1073.13 371.77,1066.43 367.68,1062.34 333.85,1062.34 329.13,1057.62 329.13,1051.47 334.78,1045.82 384.76,1045.82 404.5,1026.08 404.5,952.3 418.84,937.96 436.8,937.96 441.89,932.88 441.89,924.92 434.56,917.6 415.31,917.6 409.25,911.54 409.25,900.35 415,894.6 452.43,894.6 458.43,888.61 458.43,878.89 465.57,871.75 475.49,871.75 483,879.26 483,891.91 467,907.91 467,933.6 440.63,959.97 v1(427.06,959.97)
  Bottom Layer w5.9: U10.7@361.83,970.53 401.59,970.53 412.15,959.97 v1(427.06,959.97)
RADAR_LVDS_FRCLK: U14.7 U15.17 | length 963.3
  Top Layer w5.9: U14.7@576.39,970.53 542.14,970.53 528.92,957.3 528.92,873.29 523.23,867.6 508.35,867.6 502,873.95 502,925.8 449,978.8 449,1025.66 426.05,1048.6 398.92,1048.6 386.84,1060.69 386.84,1091.75 394.76,1099.67 407.38,1099.67 414.69,1092.36 414.69,1079.27 421.69,1072.27 433.69,1072.27 441.69,1080.27 441.69,1093.3 448,1099.6 463,1099.6 468.69,1093.91 468.69,1075.9 474.33,1070.27 486.69,1070.27 493.69,1077.27 493.69,1092.3 503,1101.6 552.56,1101.6 570.56,1119.61 570.56,1142.11 540.9,1171.78 540.9,1247.81 578.83,1285.74 U15.17@620.85,1285.74
RADAR_LVDS_FRCLKM: R220.2 U14.5 | length 672.1
  Top Layer w4: U14.5@576.39,870.53 576.39,888.43 578.74,890.77 619.25,890.77 631.14,902.66 631.14,1027.72 608.64,1050.22 579.89,1050.22 576.37,1053.74 576.37,1063.06 584.6,1071.29 613.09,1071.29 657.64,1026.73 657.64,1018.22 644.84,1005.41 644.84,931.59 653.7,922.72 671.47,922.72 681.32,932.57 681.32,951.05 690.61,960.34 701.72,960.34 707.92,954.14 v1(711.06,954.14)
  Bottom Layer w4: v1(711.06,954.14) 713.44,954.14 713.44,954.65 721.77,962.98 739.9,962.98 751.71,951.17 779.71,951.17 789.06,941.82 R220.2@789.06,941.33
RADAR_LVDS_FRCLKP: R219.2 U14.6 | length 671.1
  Top Layer w4: U14.6@576.39,920.53 576.39,903.11 578.74,900.77 615.11,900.77 621.14,906.8 621.14,1023.57 604.49,1040.22 575.75,1040.22 566.37,1049.6 566.37,1067.2 580.46,1081.29 617.23,1081.29 667.64,1030.88 667.64,1014.07 654.84,1001.27 654.84,935.73 657.85,932.72 667.33,932.72 671.32,936.71 671.32,955.19 686.47,970.34 699.83,970.34 708.36,978.87 v1(712.05,978.87)
  Bottom Layer w4: v1(712.05,978.87) 715.5,978.87 721.39,972.98 744.04,972.98 755.85,961.17 779.71,961.17 789.06,970.52 R219.2@789.06,971.01
RADAR_NRST: C60.2 J8.10 J9.9 R20.1 R171.2 R176.1 U1.M3 U1.M4 U17.4 | length 5326.1
  Top Layer w4: U1.M3@-526.56,875.94 U1.M4@-546.24,875.94 -546.35,876.05 -565.81,876.05 -587.15,897.39 -587.15,933.8 -578.47,942.49 -228.77,942.49 -209.31,923.02 C60.2@-209.31,896.44 ; R20.1@-209.11,861.86 -209.11,896.25 C60.2@-209.31,896.44 ; v1(-174.11,897.49) -208.26,897.49 C60.2@-209.31,896.44
  Top Layer w5.9: v1(422.03,345.55) 452.67,314.92 452.67,242.92 486.32,209.27 R171.2@486.32,182.97 ; J9.9@1147.1,1335.77 1150.33,1332.54 1150.33,1299.76 v1(1152.64,1297.45) ; U17.4@1469.21,1073.44 1469.61,1073.84 1469.61,1085.83 1478.1,1094.32 1478.1,1101.33 v1(1480.41,1103.65)
  Int2 (PWR) w5.9: v1(75.02,851.27) 80,851.27 129.64,851.27 156.98,878.62 156.98,962.76 45.66,1074.08 45.66,1250.77 103.74,1308.85 159.66,1308.85 190.64,1339.83 678.83,1339.83 682.62,1336.04 725.01,1336.04 747.38,1358.41 831.78,1358.41 863.45,1390.08 v1(924.41,1390.08) ; v1(422.03,345.55) 446.08,321.51 806.66,321.51 878.08,250.08 928.84,250.08 932.3,253.54 932.3,386.35 1057.75,511.81 1097.9,511.81 1105.36,519.27 1105.36,670.76 1070.76,705.36 1030.81,705.36 1002.05,734.13 1002.05,906 981.88,926.17 981.88,941.04 994.6,953.75 1022.5,953.75 1064.74,996 v1(1064.74,1014.54) 1383.92,1014.54 1400.82,1031.45 1400.82,1110.67 1413.16,1123 1461.06,1123 v1(1480.41,1103.65)
  Bottom Layer w5.9: v1(-174.11,897.49) -173,898.6 -173,911.94 -167.44,917.51 J8.10@-124.58,917.51 -76.87,917.51 -67.27,907.9 -67.27,885.62 -35.87,854.22 54.22,854.22 57.16,851.27 v1(75.02,851.27) ; v1(924.41,1390.08) 926.72,1387.76 926.72,1372.81 969.93,1329.6 1120.49,1329.6 v1(1152.64,1297.45) 1152.64,1283.72 1142.51,1273.59 1102.03,1273.59 1082.37,1253.93 1082.37,1211.02 1082.37,1107.01 1052.09,1076.73 1052.09,1027.19 v1(1064.74,1014.54) ; v1(1480.41,1103.65) 1480.48,1103.72 1480.48,1117.16 1483.94,1120.61 R176.1@1501.25,1120.61
RADAR_NRST_1: R63.1 R123.1 U17.1 | length 954.5
  Top Layer w5.9: v1(1413.21,998.48) 1413.21,998.79 1405,1007 1405,1032.99 1405.87,1033.86 1421.41,1033.86 1433.31,1021.96 1438.2,1021.96 1441.65,1025.41 U17.1@1441.65,1041.94
  Int2 (PWR) w5.9: v1(1309.37,569.12) 1329.1,588.86 1329.1,617.55 1317.97,628.69 1317.97,748.26 1303.74,762.49 1283.65,762.49 1270,748.84 1207.14,748.84 1155.54,800.44 1155.54,932.95 1221.07,998.48 v1(1413.21,998.48)
  Bottom Layer w5.9: R63.1@1262.19,581.08 1262.75,580.52 1297.97,580.52 v1(1309.37,569.12)
RADAR_NRST_2: C53.1 R165.1 R243.2 S2.3 S2.4 U17.6 | length 1907.7
  Top Layer w5.9: S2.3@777.5,230.02 777.5,193.1 804.26,166.34 R165.1@909.27,166.34 953.88,166.34 C53.1@954,166.22 954,215.6 968.42,230.02 S2.4@1090.49,230.02 1090.49,335.6 1147.71,392.82 1147.71,542.35 v1(1160.6,555.24) ; U17.6@1441.65,1073.44 1442.05,1073.84 1442.05,1103.27 v1(1442.86,1104.08) ; v1(1453,621) 1522.3,621 1540.25,638.95 R243.2@1540.25,663.99
  Int2 (PWR) w5.9: v1(1160.6,555.24) 1228.94,555.24 1241.28,567.58 1285.53,567.58 1305.43,547.67 1323.43,547.67 1350.14,574.38 1350.14,617.61 1361.65,629.11 1403.77,629.11 1411.89,621 v1(1453,621) 1453,649 1432.38,669.62 1432.38,748.75 1480.45,796.83 1480.45,973.51 1546.2,1039.26 1546.2,1039.58 1548.36,1041.74 1548.36,1057.66 1536.2,1069.82 1477.12,1069.82 v1(1442.86,1104.08)
RADAR_OSC_CLKOUT: TP5.1 U1.A8 U1.B8 | length 81.7
  Top Layer w10: U1.A8@-851.36,659.41 U1.B8@-851.36,679.09
  Bottom Layer w10: v1(-851.04,669.25) -851.04,641.64 TP5.1@-826.71,617.3
RADAR_SRAM_1V2: C25.2 C26.2 R77.1 U1.M1 U1.M2 U1.N2 | length 56.9
  Top Layer w10: v1(-505.34,912.48) -506.48,911.33 -506.48,895.7 -506.56,895.63 v1(-506.56,885.79) -506.87,885.47 U1.M2@-506.87,875.94 U1.M1@-487.19,875.94
RADAR_VBGAP: C6.1 U1.H10 | length 21.7
  Top Layer w12: v1(-910.16,791.8) -909.08,791.8 -904.22,796.66 -899.9,796.66 -899.36,797.2 U1.H10@-890.73,797.2
REF_FTDI: R218.2 U27.6 | length 246.6
  Top Layer w5.9: U27.6@2077.62,703.36 2116.75,703.36 2125.45,712.06 2125.45,739.16 2149.44,763.15 2246.09,763.15 2259.91,776.96 R218.2@2259.91,794.95
REG_1V2: C61.2 L5.2 R193.1 U8.8 U8.10 | length 269.4
  Bottom Layer w10: U8.8@801.28,159.91 766.31,159.91 758,151.6 758,130.39 767.3,121.09 800.73,121.09 U8.10@801.28,120.54 863.72,120.54 894.64,89.62 903.2,81.06 R193.1@908.71,81.06 ; R193.1@882.71,77.69 R193.1@904.18,99.16
REG_1V8: C68.2 L6.2 R9.1 R192.1 U6.8 U6.10 | length 280.3
  Bottom Layer w11: R192.1@2258.92,224.04 2257.06,224.04 R192.1@2256.59,224.51 2262.1,224.51 2303.5,183.11 ; U6.8@2337.55,139.04 2337.95,139.45 2375.55,139.45 2382,145.89 2382,165.75 2369.74,178.01 2337.95,178.01 U6.10@2337.55,178.41
  Bottom Layer w12: 2303.5,183.11 2308.11,178.51 2337.45,178.51 U6.10@2337.55,178.41
  Bottom Layer w15: R9.1@2181.42,46.65 2181.53,46.76 2181.53,107.34 C68.2@2181.65,107.45
REG_MODE_SELECT: R173.2 U24.8 | length 2078.8
  Top Layer w5.9: v1(68.05,605.44) 68.05,699.99 90.35,722.29 v1(90.35,722.49) ; R173.2@1200.25,369.83 1200.25,393.25 1206,399 1206,405.21 v1(1205.77,405.44)
  Int2 (PWR) w5.9: v1(68.05,605.44) 114.37,605.44 217.21,502.6 252.91,502.6 361.4,394.11 361.4,366.2 417.99,309.61 801.73,309.61 873.15,238.18 933.77,238.18 944.2,248.61 944.2,381.42 1061.29,498.52 1135.49,498.52 1140.52,493.49 1205.77,428.24 v1(1205.77,405.44)
  Bottom Layer w5.9: v1(90.35,722.49) 90.55,722.29 103.87,722.29 140.28,758.7 140.28,877.15 151.31,888.17 151.31,1007.52 176.64,1032.85 176.64,1049.04 U24.8@176.78,1049.18
REG_OUT_1V2: C100.1 C119.1 C120.1 C121.2 C122.2 L1.1 L5.1 L14.2 R119.2
REG_OUT_1V8: C1.1 C128.1 C129.1 C130.2 C131.2 L6.1 L15.2 R35.1 | length 473
  Int2 (PWR) w10: v1(2421,524.6) 2421,373.42 2475.78,318.64 v1(2514.46,318.64)
  Bottom Layer w10: v1(2421,524.6) 2422.53,526.13 2517.4,526.13 2520.27,529.01 2520.27,532.44 2521.26,533.43 2521.26,574.61 C1.1@2522.25,575.6 ; L15.2@2471.34,286.26 2483.15,286.26 2514.46,317.57 v1(2514.46,318.64)
REG_PG: R175.1 R176.2 U19.6 U20.6 | length 2684.2
  Top Layer w5.9: v1(1352.12,310.73) 1352.12,357.74 1400.17,405.79 v1(1414.2,405.79)
  Int2 (PWR) w5.9: v1(1553.57,1078.53) 1572.86,1078.53 1585.63,1065.76 1585.63,1026.55 1570.35,1011.27 1561.42,1011.27 1556.18,1016.51 1541.4,1016.51 1498.1,973.21 1498.1,612.94 1472.97,587.81 1422.35,587.81 1338.46,503.92 1338.46,463.93 1396.59,405.79 v1(1414.2,405.79) 1429.46,390.53 1467.13,390.53 1521.48,444.88 1542.71,444.88 1587.89,399.7 1631.85,399.7 1736.6,504.45 1844.48,504.45 1865.32,483.61 2326,483.61 2387.88,545.48 2495.48,545.48 v1(2603.17,437.79)
  Bottom Layer w5.9: U19.6@1330.05,360.08 1330.05,341.1 1350.84,320.3 1350.84,312.01 v1(1352.12,310.73) ; R175.1@1510.91,1155.09 1512.28,1153.72 1529.28,1153.72 1540.62,1142.38 1540.62,1092.53 1553.57,1079.57 v1(1553.57,1078.53) ; U20.6@2508.43,404.76 2508.43,385.86 2512.24,382.06 2547.44,382.06 v1(2603.17,437.79)
REG_RF_1V2: C79.2 L1.2 R134.1 U25.8 U25.10 | length 219.5
  Bottom Layer w12: R134.1@1522.76,80.45 1553.58,111.28 1553.58,211.46 1560.61,218.49 1582.59,218.49 1592.86,208.22 1592.86,201.49 1592.95,201.4 U25.8@1592.95,178.95
RST_FTDI: R237.2 U27.14 | length 188.7
  Top Layer w5.9: R237.2@2047,1001.11 2047,923.5 2032.5,909.01 2032.5,865.49 2037.16,860.84 U27.14@2077.62,860.84
RTC_CLKIN: TP3.1 U15.19 | length 145.7
  Top Layer w5.9: U15.19@620.85,1336.92 717.19,1336.92 TP3.1@752.1,1371.83
SOP0_FTDI: R249.1 U27.55 | length 102.4
  Top Layer w5.9: U27.55@1829.58,534.06 1829.58,490.53 1856.53,463.58 R249.1@1877.3,463.58
SOP0_H: R204.1 SW1.1 | length 60.7
  Top Layer w5.9: R204.1@1237.83,212.89 1238.37,212.35 SW1.1@1298.34,212.35
SOP0_L: R205.2 SW1.3 | length 100.6
  Top Layer w5.9: SW1.3@1495.2,212.35 1495.2,182.89 1501.49,176.6 R205.2@1563.73,176.6
SOP1_FTDI: R248.1 U27.54 | length 105.1
  Top Layer w5.9: U27.54@1809.9,534.06 1809.9,477.87 1828.69,459.07 R248.1@1828.69,436.71
SPI_MUX_ENn: R10.1 U28.20 | length 62.4
  Bottom Layer w5.9: R10.1@579.31,1522.09 R10.1@581.03,1520.36 U28.20@581.03,1460.36
SW2: L14.1 U19.7 | length 55.2
  Bottom Layer w11: L14.1@1305.48,306.95 1310.36,311.83 U19.7@1310.36,360.08
SW3: L15.1 U20.7
SW_PR1: R102.1 R120.2 U16.4 | length 119.5
  Top Layer w5.9: U16.4@2285.53,273.47 2285.54,292.13 2298.46,305.05 2315.17,305.05 2321.22,299 R102.1@2321.22,281.65 R120.2@2361.22,281.65
SW_ST: R76.1 TP8.1 U16.8 | length 117.2
  Top Layer w5.9: TP8.1@2145.55,375.86 2148.8,372.62 R76.1@2186.89,372.62 ; R76.1@2187.1,372.41 2187.89,371.62 2187.89,357.38 2192.21,353.06 2222.21,353.06 2225.67,349.6 2225.67,332.54 U16.8@2226.47,331.74
TS3A_ENn: R91.1 U15.20 | length 150.5
  Top Layer w5.9: U15.20@620.87,1362.5 665.7,1362.5 669.27,1366.07 v1(694.8,1366.07)
  Bottom Layer w5.9: v1(694.8,1366.07) 722.78,1366.07 733.75,1377.04 R91.1@765.35,1377.04
USB_5V: C86.2 J5.1 L9.1 | length 39.7
  Top Layer w20: L9.1@2871.65,1073.09 2871.65,1074.75 2871.81,1074.9 2873.46,1074.9 2876.03,1077.47 C86.2@2908.53,1077.47
USER_LED_SW_GPIO_0: R66.2 R214.2 R242.2 U24.11 | length 4669.5
  Top Layer w5.9: v1(142.18,1110.02) 142.18,1088.75 126.64,1073.21 126.64,984.54 183.27,927.91 183.27,821.94 169.86,808.54 169.86,674.57 220.91,623.52 267.62,623.52 295.34,595.79 295.34,563.64 326.92,532.06 359.84,532.06 v1(371.7,543.92) 425.9,489.72 486.65,489.72 499.29,502.35 600.68,502.35 673.24,574.91 948.53,574.91 969.1,554.34 969.1,490.53 937.58,459.01 728.41,459.01 712.08,442.69 712.08,258.96 687.94,234.82 687.94,79.66 711.57,56.03 993.6,56.03 1037.31,99.74 R66.2@1037.31,122.6 ; v1(1087.13,558.01) 1118.28,558.01 1148.45,588.19 R214.2@1184,588.19 ; v1(1410.3,651.44) 1444.98,651.44 1455.97,640.45 1485.53,640.45 1528.09,683.01 v1(1560.43,683.01) ; v1(1738.57,372.78) 1738.57,354.55 1760.5,332.62 1835.75,332.62 1873.66,370.54 1883.95,370.54 1920.82,407.41 1920.82,422.07 R242.2@1920.74,422.16
  Int2 (PWR) w5.9: v1(371.7,543.92) 445.11,470.5 999.62,470.5 v1(1087.13,558.01)
  Bottom Layer w5.9: v1(142.18,1110.02) 142.36,1110.02 148.09,1104.3 U24.11@168.91,1104.3 ; v1(1087.13,558.01) 1102.3,573.19 1184.58,573.19 1195.19,562.58 1272.39,562.58 1283.8,551.17 1318.73,551.17 1336.86,569.31 1336.86,609.83 1379.03,652 1409.73,652 v1(1410.3,651.44) ; v1(1560.43,683.01) 1608.09,635.35 1608.09,562.44 1694.26,476.27 1694.26,417.09 v1(1738.57,372.78)
VBAT: J4.2 R32.1
VBUS_1_DETECT: C118.2 R236.1 R239.2 U21.1 | length 122.3
  Bottom Layer w8: C118.2@1858.68,628.6 1860.37,630.29 1921.18,630.29 U21.1@1921.25,630.36
  Bottom Layer w20: C118.2@1858.68,628.6 R236.1@1858.68,687.6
